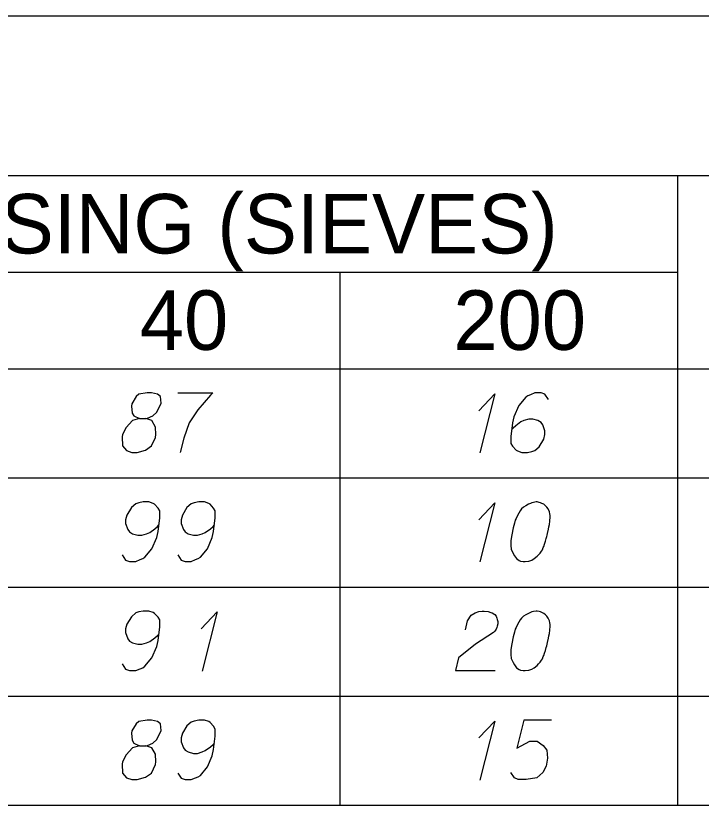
# Model space of a CAD drawing. Extents: x 2074207 to 2076812, y 516372 to 523312.
# Drawn here: x 2076678.5 to 2076733.8, y 517484.4 to 517548.1 of the extents above; entities that cross this region are included whole.
import ezdxf

# ---------------------------------------------------------------- set-up
doc = ezdxf.new("R2010")
doc.units = 0
for name, color, linetype in [('Prop DirtTable_ Soil Test Results - Outline (Major)', 7, 'Continuous'), ('Prop DirtTable_ Soil Test Results - Outline (Minor)', 7, 'Continuous'), ('Prop DirtTable_ Soil Test Results - Tx (Header - Small)', 7, 'Continuous'), ('Prop DirtTable_ Soil Test Results - Tx (Sample Data)', 7, 'Continuous')]:
    doc.layers.add(name, color=color, linetype=linetype)

msp = doc.modelspace()

# ---------------------------------------------------------------- linework, layer by layer
at = {"layer": 'Prop DirtTable_ Soil Test Results - Outline (Major)'}
for p, q in [((2076260.609, 517548.096), (2076811.903, 517548.096)), ((2076260.609, 517519.61), (2076811.903, 517519.61)), ((2076260.609, 517519.61), (2076811.903, 517519.61)), ((2076260.609, 517484.41), (2076811.903, 517484.41))]:
    msp.add_line(p, q, dxfattribs=at)
at = {"layer": 'Prop DirtTable_ Soil Test Results - Outline (Minor)'}
for p, q in [((2076260.609, 517535.21), (2076811.903, 517535.21)), ((2076731.93, 517535.21), (2076731.93, 517510.81)), ((2076526.074, 517527.41), (2076731.93, 517527.41)), ((2076704.671, 517527.41), (2076704.671, 517510.81)), ((2076260.609, 517510.81), (2076811.903, 517510.81)), ((2076260.609, 517510.81), (2076811.903, 517510.81)), ((2076704.671, 517510.81), (2076704.671, 517502.01)), ((2076731.93, 517510.81), (2076731.93, 517502.01)), ((2076260.609, 517502.01), (2076811.903, 517502.01)), ((2076260.609, 517502.01), (2076811.903, 517502.01)), ((2076704.671, 517502.01), (2076704.671, 517493.21)), ((2076731.93, 517502.01), (2076731.93, 517493.21)), ((2076260.609, 517493.21), (2076811.903, 517493.21)), ((2076260.609, 517493.21), (2076811.903, 517493.21)), ((2076704.671, 517493.21), (2076704.671, 517484.41)), ((2076731.93, 517493.21), (2076731.93, 517484.41)), ((2076260.609, 517484.41), (2076811.903, 517484.41))]:
    msp.add_line(p, q, dxfattribs=at)
at = {"layer": 'Prop DirtTable_ Soil Test Results - Tx (Sample Data)'}
for points in [[(2076688.527, 517515.595), (2076689.02, 517515.595), (2076689.162, 517515.633), (2076689.585, 517515.822), (2076689.902, 517516.124), (2076690.255, 517516.842), (2076690.22, 517517.371), (2076689.973, 517517.56), (2076689.479, 517517.674), (2076689.126, 517517.674), (2076688.456, 517517.56), (2076688.244, 517517.371), (2076687.892, 517516.804), (2076687.856, 517516.615), (2076687.927, 517516.048), (2076688.068, 517515.822), (2076688.527, 517515.595), (2076687.962, 517515.444), (2076687.433, 517514.877), (2076687.151, 517514.31), (2076687.116, 517514.121), (2076687.151, 517513.403), (2076687.468, 517513.025), (2076687.892, 517512.874), (2076688.315, 517512.874), (2076688.985, 517513.063), (2076689.479, 517513.403), (2076689.797, 517514.083), (2076689.832, 517514.31), (2076689.797, 517514.915), (2076689.514, 517515.444), (2076689.02, 517515.595)], [(2076691.596, 517517.674), (2076694.418, 517517.674), (2076694.241, 517517.485), (2076693.218, 517516.313), (2076692.513, 517515.255), (2076692.089, 517514.008), (2076691.807, 517512.874)], [(2076715.9, 517516.237), (2076717.17, 517517.598), (2076715.971, 517512.836)], [(2076721.509, 517517.145), (2076721.227, 517517.56), (2076720.91, 517517.674), (2076720.416, 517517.674), (2076720.063, 517517.522), (2076719.851, 517517.447), (2076719.675, 517517.333), (2076719.111, 517516.653), (2076718.723, 517515.746), (2076718.617, 517515.255), (2076718.476, 517514.159), (2076718.476, 517513.592), (2076718.617, 517513.365), (2076718.899, 517513.063), (2076719.005, 517512.987), (2076719.358, 517512.874), (2076719.816, 517512.874), (2076720.169, 517512.949), (2076720.416, 517513.025), (2076720.769, 517513.327), (2076721.121, 517513.932), (2076721.227, 517514.31), (2076721.227, 517514.612), (2076721.051, 517515.104), (2076720.91, 517515.293), (2076720.663, 517515.444), (2076720.239, 517515.557), (2076719.922, 517515.557), (2076719.534, 517515.444), (2076719.287, 517515.33), (2076718.864, 517515.028), (2076718.652, 517514.839), (2076718.546, 517514.726)], [(2076687.116, 517504.603), (2076687.398, 517504.187), (2076687.715, 517504.074), (2076688.209, 517504.074), (2076688.562, 517504.225), (2076688.774, 517504.3), (2076688.95, 517504.414), (2076689.514, 517505.094), (2076689.902, 517506.001), (2076690.008, 517506.493), (2076690.149, 517507.589), (2076690.149, 517508.156), (2076690.008, 517508.382), (2076689.726, 517508.685), (2076689.62, 517508.76), (2076689.267, 517508.874), (2076688.809, 517508.874), (2076688.456, 517508.798), (2076688.209, 517508.722), (2076687.856, 517508.42), (2076687.504, 517507.815), (2076687.398, 517507.437), (2076687.398, 517507.135), (2076687.574, 517506.644), (2076687.715, 517506.455), (2076687.962, 517506.304), (2076688.386, 517506.19), (2076688.703, 517506.19), (2076689.091, 517506.304), (2076689.338, 517506.417), (2076689.761, 517506.719), (2076689.973, 517506.908), (2076690.079, 517507.022)], [(2076691.596, 517504.603), (2076691.878, 517504.187), (2076692.195, 517504.074), (2076692.689, 517504.074), (2076693.042, 517504.225), (2076693.254, 517504.3), (2076693.43, 517504.414), (2076693.994, 517505.094), (2076694.382, 517506.001), (2076694.488, 517506.493), (2076694.629, 517507.589), (2076694.629, 517508.156), (2076694.488, 517508.382), (2076694.206, 517508.685), (2076694.1, 517508.76), (2076693.747, 517508.874), (2076693.289, 517508.874), (2076692.936, 517508.798), (2076692.689, 517508.722), (2076692.336, 517508.42), (2076691.984, 517507.815), (2076691.878, 517507.437), (2076691.878, 517507.135), (2076692.054, 517506.644), (2076692.195, 517506.455), (2076692.442, 517506.304), (2076692.866, 517506.19), (2076693.183, 517506.19), (2076693.571, 517506.304), (2076693.818, 517506.417), (2076694.241, 517506.719), (2076694.453, 517506.908), (2076694.559, 517507.022)], [(2076720.592, 517508.874), (2076720.522, 517508.874), (2076720.31, 517508.836), (2076720.169, 517508.798), (2076720.063, 517508.76), (2076719.887, 517508.685), (2076719.675, 517508.571), (2076719.499, 517508.458), (2076719.322, 517508.307), (2076719.216, 517508.156), (2076719.111, 517507.967), (2076719.005, 517507.778), (2076718.899, 517507.551), (2076718.828, 517507.4), (2076718.758, 517507.173), (2076718.652, 517506.795), (2076718.546, 517506.228), (2076718.476, 517505.774), (2076718.476, 517505.359), (2076718.511, 517505.056), (2076718.652, 517504.716), (2076718.758, 517504.527), (2076718.934, 517504.3), (2076719.146, 517504.149), (2076719.252, 517504.111), (2076719.463, 517504.074), (2076719.64, 517504.074), (2076719.922, 517504.111), (2076720.169, 517504.187), (2076720.345, 517504.3), (2076720.592, 517504.489), (2076720.698, 517504.603), (2076720.839, 517504.754), (2076720.945, 517504.905), (2076721.015, 517505.019), (2076721.086, 517505.208), (2076721.121, 517505.283), (2076721.192, 517505.472), (2076721.262, 517505.699), (2076721.333, 517505.926), (2076721.368, 517506.077), (2076721.403, 517506.19), (2076721.439, 517506.341), (2076721.509, 517506.682), (2076721.545, 517506.87), (2076721.58, 517507.059), (2076721.615, 517507.324), (2076721.65, 517507.664), (2076721.65, 517507.778), (2076721.615, 517507.929), (2076721.58, 517508.08), (2076721.474, 517508.307), (2076721.368, 517508.458), (2076721.262, 517508.571), (2076721.121, 517508.685), (2076720.98, 517508.76), (2076720.874, 517508.798), (2076720.769, 517508.836), (2076720.592, 517508.874)], [(2076715.9, 517507.437), (2076717.17, 517508.798), (2076715.971, 517504.036)], [(2076687.116, 517495.803), (2076687.398, 517495.387), (2076687.715, 517495.274), (2076688.209, 517495.274), (2076688.562, 517495.425), (2076688.774, 517495.5), (2076688.95, 517495.614), (2076689.514, 517496.294), (2076689.902, 517497.201), (2076690.008, 517497.693), (2076690.149, 517498.789), (2076690.149, 517499.356), (2076690.008, 517499.582), (2076689.726, 517499.885), (2076689.62, 517499.96), (2076689.267, 517500.074), (2076688.809, 517500.074), (2076688.456, 517499.998), (2076688.209, 517499.922), (2076687.856, 517499.62), (2076687.504, 517499.015), (2076687.398, 517498.637), (2076687.398, 517498.335), (2076687.574, 517497.844), (2076687.715, 517497.655), (2076687.962, 517497.504), (2076688.386, 517497.39), (2076688.703, 517497.39), (2076689.091, 517497.504), (2076689.338, 517497.617), (2076689.761, 517497.919), (2076689.973, 517498.108), (2076690.079, 517498.222)], [(2076693.5, 517498.637), (2076694.77, 517499.998), (2076693.571, 517495.236)], [(2076714.807, 517498.562), (2076714.983, 517499.28), (2076715.266, 517499.733), (2076715.583, 517499.922), (2076715.9, 517500.036), (2076716.147, 517500.074), (2076716.324, 517500.074), (2076716.641, 517500.036), (2076716.853, 517499.96), (2076716.959, 517499.922), (2076717.17, 517499.809), (2076717.276, 517499.658), (2076717.347, 517499.507), (2076717.382, 517499.393), (2076717.417, 517499.242), (2076717.417, 517499.053), (2076717.382, 517498.864), (2076717.347, 517498.751), (2076717.276, 517498.6), (2076717.17, 517498.448), (2076717.065, 517498.335), (2076715.618, 517497.39), (2076714.243, 517496.294), (2076713.996, 517495.274), (2076717.206, 517495.274)], [(2076720.592, 517500.074), (2076720.522, 517500.074), (2076720.31, 517500.036), (2076720.169, 517499.998), (2076720.063, 517499.96), (2076719.887, 517499.885), (2076719.675, 517499.771), (2076719.499, 517499.658), (2076719.322, 517499.507), (2076719.216, 517499.356), (2076719.111, 517499.167), (2076719.005, 517498.978), (2076718.899, 517498.751), (2076718.828, 517498.6), (2076718.758, 517498.373), (2076718.652, 517497.995), (2076718.546, 517497.428), (2076718.476, 517496.974), (2076718.476, 517496.559), (2076718.511, 517496.256), (2076718.652, 517495.916), (2076718.758, 517495.727), (2076718.934, 517495.5), (2076719.146, 517495.349), (2076719.252, 517495.311), (2076719.463, 517495.274), (2076719.64, 517495.274), (2076719.922, 517495.311), (2076720.169, 517495.387), (2076720.345, 517495.5), (2076720.592, 517495.689), (2076720.698, 517495.803), (2076720.839, 517495.954), (2076720.945, 517496.105), (2076721.015, 517496.219), (2076721.086, 517496.408), (2076721.121, 517496.483), (2076721.192, 517496.672), (2076721.262, 517496.899), (2076721.333, 517497.126), (2076721.368, 517497.277), (2076721.403, 517497.39), (2076721.439, 517497.541), (2076721.509, 517497.882), (2076721.545, 517498.07), (2076721.58, 517498.259), (2076721.615, 517498.524), (2076721.65, 517498.864), (2076721.65, 517498.978), (2076721.615, 517499.129), (2076721.58, 517499.28), (2076721.474, 517499.507), (2076721.368, 517499.658), (2076721.262, 517499.771), (2076721.121, 517499.885), (2076720.98, 517499.96), (2076720.874, 517499.998), (2076720.769, 517500.036), (2076720.592, 517500.074)], [(2076688.527, 517489.195), (2076689.02, 517489.195), (2076689.162, 517489.233), (2076689.585, 517489.422), (2076689.902, 517489.724), (2076690.255, 517490.442), (2076690.22, 517490.971), (2076689.973, 517491.16), (2076689.479, 517491.274), (2076689.126, 517491.274), (2076688.456, 517491.16), (2076688.244, 517490.971), (2076687.892, 517490.404), (2076687.856, 517490.215), (2076687.927, 517489.648), (2076688.068, 517489.422), (2076688.527, 517489.195), (2076687.962, 517489.044), (2076687.433, 517488.477), (2076687.151, 517487.91), (2076687.116, 517487.721), (2076687.151, 517487.003), (2076687.468, 517486.625), (2076687.892, 517486.474), (2076688.315, 517486.474), (2076688.985, 517486.663), (2076689.479, 517487.003), (2076689.797, 517487.683), (2076689.832, 517487.91), (2076689.797, 517488.515), (2076689.514, 517489.044), (2076689.02, 517489.195)], [(2076691.596, 517487.003), (2076691.878, 517486.587), (2076692.195, 517486.474), (2076692.689, 517486.474), (2076693.042, 517486.625), (2076693.254, 517486.7), (2076693.43, 517486.814), (2076693.994, 517487.494), (2076694.382, 517488.401), (2076694.488, 517488.893), (2076694.629, 517489.989), (2076694.629, 517490.556), (2076694.488, 517490.782), (2076694.206, 517491.085), (2076694.1, 517491.16), (2076693.747, 517491.274), (2076693.289, 517491.274), (2076692.936, 517491.198), (2076692.689, 517491.122), (2076692.336, 517490.82), (2076691.984, 517490.215), (2076691.878, 517489.837), (2076691.878, 517489.535), (2076692.054, 517489.044), (2076692.195, 517488.855), (2076692.442, 517488.704), (2076692.866, 517488.59), (2076693.183, 517488.59), (2076693.571, 517488.704), (2076693.818, 517488.817), (2076694.241, 517489.119), (2076694.453, 517489.308), (2076694.559, 517489.422)], [(2076715.9, 517489.837), (2076717.17, 517491.198), (2076715.971, 517486.436)], [(2076721.756, 517491.274), (2076719.534, 517491.274), (2076718.969, 517489.006), (2076719.992, 517489.573), (2076720.592, 517489.573), (2076721.086, 517489.233), (2076721.368, 517488.855), (2076721.439, 517488.212), (2076721.333, 517487.57), (2076721.051, 517487.041), (2076720.557, 517486.625), (2076719.71, 517486.474), (2076719.075, 517486.474), (2076718.758, 517486.625), (2076718.476, 517487.041)]]:
    msp.add_lwpolyline(points, dxfattribs=at)

# ---------------------------------------------------------------- texts
at = {"layer": 'Prop DirtTable_ Soil Test Results - Tx (Header - Small)'}
for s, height, p in [('% PASSING (SIEVES)', 4.79998, (2076656.984, 517528.921)), ('40', 4.8, (2076688.534, 517521.145)), ('200', 4.8, (2076713.832, 517521.145))]:
    msp.add_text(s, height=height, dxfattribs=at).set_placement(p)

doc.saveas('drawing.dxf')
